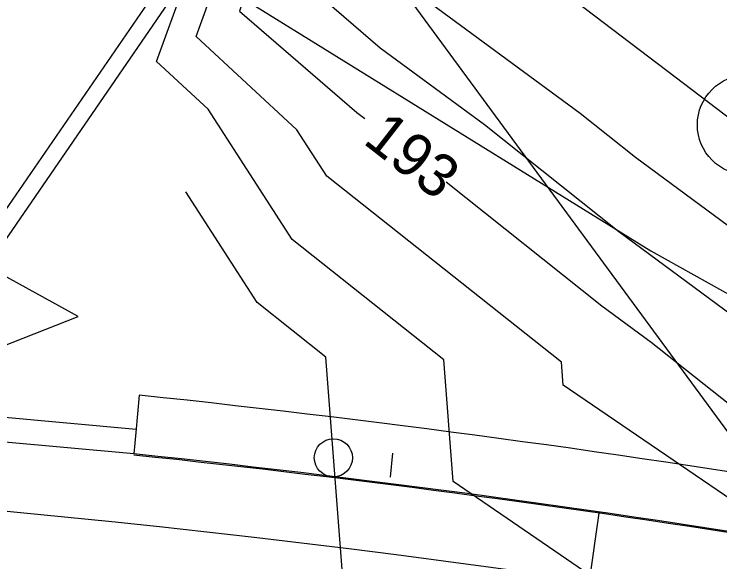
# Model space of a CAD drawing. Extents: x 1385284 to 1385995, y 1975154 to 1975620.
# Drawn here: x 1385581.75 to 1385622.84, y 1975494.43 to 1975526.32 of the extents above; entities that cross this region are included whole.
import ezdxf

# ---------------------------------------------------------------- set-up
doc = ezdxf.new("R2010")
doc.units = 0
for name, color, linetype in [('B-Super-Deck', 7, 'Continuous'), ('Default', 7, 'Continuous'), ('DTM CONTOURS_MAJOR', 7, 'Continuous'), ('DTM_CONTOURS_MINOR', 7, 'Continuous'), ('R_Guardrail', 7, 'Continuous'), ('R_Proposed Road', 7, 'Continuous'), ('R_Shld', 7, 'Continuous'), ('S_IRON_PIN', 7, 'Continuous'), ('S_UNDERGROUND_CABLE', 7, 'Continuous'), ('S_WATER_UTILITIES', 7, 'Continuous')]:
    doc.layers.add(name, color=color, linetype=linetype)

msp = doc.modelspace()

# ---------------------------------------------------------------- linework, layer by layer
at = {"layer": 'B-Super-Deck'}
for p, q in [((1385588.853, 1975502.134), (1385578.894, 1975503.042)), ((1385588.838, 1975501.968), (1385588.724, 1975500.723)), ((1385588.724, 1975500.723), (1385578.766, 1975501.631))]:
    msp.add_line(p, q, dxfattribs=at)
at = {"layer": 'Default'}
for p, q in [((1385601.664, 1975544.642), (1385558.992, 1975482.58)), ((1385559.816, 1975482.013), (1385602.488, 1975544.075)), ((1385603.662, 1975499.361), (1385603.791, 1975500.772))]:
    msp.add_line(p, q, dxfattribs=at)
at = {"layer": 'DTM CONTOURS_MAJOR'}
for points in [[(1385603.84, 1975543.794), (1385602.41, 1975541.146), (1385602.075, 1975540.135), (1385601.205, 1975538.235), (1385601.153, 1975536.854), (1385603.587, 1975531.903), (1385602.776, 1975529.562), (1385604.437, 1975528.129), (1385614.7, 1975520.562), (1385617.932, 1975517.988), (1385628.308, 1975510.325), (1385631.416, 1975507.862), (1385642.381, 1975499.714), (1385644.646, 1975497.454), (1385655.57, 1975489.358), (1385657.86, 1975487.03), (1385667.487, 1975479.873), (1385669.851, 1975478.374)], [(1385567.349, 1975435.532), (1385575.643, 1975444.505), (1385584.2, 1975453.764), (1385584.866, 1975454.455), (1385593.445, 1975463.74), (1385594.049, 1975464.365), (1385602.648, 1975473.677), (1385603.227, 1975473.83), (1385603.894, 1975475.512), (1385603.308, 1975476.333), (1385604.191, 1975491.234), (1385600.884, 1975493.495), (1385599.902, 1975506.35), (1385595.893, 1975509.526), (1385591.739, 1975515.976)]]:
    msp.add_lwpolyline(points, dxfattribs=at)
at = {"layer": 'DTM_CONTOURS_MINOR'}
for points in [[(1385562.866, 1975481.018), (1385563.716, 1975498.339), (1385566.287, 1975500.31), (1385572.546, 1975503.642), (1385585.482, 1975508.711), (1385572.018, 1975516.132), (1385577.884, 1975524.056), (1385581.986, 1975529.59), (1385586.864, 1975537.76), (1385589.378, 1975541.298), (1385592.421, 1975550.843), (1385595.925, 1975556.919), (1385603.651, 1975570.298), (1385603.747, 1975570.566), (1385603.842, 1975570.633), (1385603.931, 1975570.594), (1385610.734, 1975574.084), (1385616.057, 1975580.707), (1385617.625, 1975582.015), (1385623.884, 1975585.062), (1385632.559, 1975588.36), (1385643.399, 1975583.605), (1385645.132, 1975583.412)], [(1385617.369, 1975492.225), (1385607.301, 1975499.112), (1385606.759, 1975506.204), (1385597.926, 1975513.203), (1385593.044, 1975520.782), (1385590.045, 1975523.554), (1385593.409, 1975532.864), (1385594.84, 1975537.505), (1385595.303, 1975538.903), (1385601.683, 1975550.713), (1385601.762, 1975550.79), (1385602.065, 1975551.447), (1385602.382, 1975552.155), (1385602.612, 1975552.619), (1385602.984, 1975553.423), (1385609.856, 1975566.014), (1385610.538, 1975566.429), (1385610.608, 1975566.793), (1385616.058, 1975574.533), (1385619.393, 1975578.242), (1385622.579, 1975579.77), (1385630.039, 1975576.498), (1385630.815, 1975576.153)], [(1385629.951, 1975571.07), (1385621.746, 1975574.571), (1385620.16, 1975573.831), (1385614.59, 1975567.03), (1385614.55, 1975566.928), (1385614.23, 1975565.243), (1385610.958, 1975563.25), (1385606.701, 1975555.45), (1385605.583, 1975553.037), (1385604.893, 1975551.643), (1385603.941, 1975549.518), (1385603.033, 1975547.546), (1385602.794, 1975547.314), (1385598.857, 1975540.024), (1385597.975, 1975537.363), (1385597.843, 1975537.074), (1385597.835, 1975536.864), (1385598.205, 1975536.11), (1385594.871, 1975526.487), (1385601.698, 1975520.596), (1385602.165, 1975520.252)], [(1385625.464, 1975571.006), (1385622.697, 1975572.187), (1385619.09, 1975570.502), (1385617.649, 1975568.743), (1385616.089, 1975564.721), (1385616.076, 1975564.65), (1385611.51, 1975561.868), (1385608.56, 1975556.464), (1385607.069, 1975553.246), (1385606.148, 1975551.388), (1385604.88, 1975548.554), (1385603.668, 1975545.924), (1385603.35, 1975545.614), (1385600.633, 1975540.585), (1385600.025, 1975538.749), (1385599.524, 1975537.654), (1385599.494, 1975536.859), (1385600.896, 1975534.007), (1385598.824, 1975528.024), (1385603.067, 1975524.362), (1385609.13, 1975519.893), (1385616.946, 1975513.668), (1385623.574, 1975508.772)], [(1385629.373, 1975493.57), (1385625.229, 1975496.854), (1385613.718, 1975504.728), (1385613.616, 1975506.059), (1385599.959, 1975516.88), (1385598.212, 1975519.591), (1385592.342, 1975525.015), (1385593.897, 1975529.32), (1385596.302, 1975537.115), (1385597.08, 1975539.464), (1385602.239, 1975549.013), (1385602.397, 1975549.168), (1385603.003, 1975550.482), (1385603.637, 1975551.899), (1385604.098, 1975552.828), (1385604.843, 1975554.436), (1385610.407, 1975564.632), (1385612.384, 1975565.836), (1385612.585, 1975566.89), (1385615.274, 1975570.71), (1385615.989, 1975571.504)], [(1385623.453, 1975555.61), (1385614.29, 1975559.46), (1385613.233, 1975559.187), (1385613.147, 1975559.43), (1385612.612, 1975559.104), (1385612.277, 1975558.491), (1385610.041, 1975553.664), (1385608.659, 1975550.876), (1385606.756, 1975546.625), (1385604.938, 1975542.679), (1385604.462, 1975542.216), (1385604.187, 1975541.707), (1385604.125, 1975541.521), (1385602.886, 1975538.815), (1385602.88, 1975538.66), (1385603.48, 1975537.236), (1385604.253, 1975534.51), (1385611.283, 1975529.471), (1385619.738, 1975523.045), (1385629.376, 1975515.719)], [(1385606.898, 1975516.565), (1385615.959, 1975509.347), (1385618.84, 1975507.219), (1385630.054, 1975498.334), (1385633.931, 1975495.453), (1385642.395, 1975487.011)]]:
    msp.add_lwpolyline(points, dxfattribs=at)
at = {"layer": 'R_Guardrail'}
msp.add_circle((1385600.333, 1975500.493), 1.109, dxfattribs=at)
msp.add_arc((1385514.363, 1974795.136), 709.494, 80.374587, 83.983855, dxfattribs=at)
at = {"layer": 'R_Proposed Road'}
msp.add_line((1385615.796, 1975497.271), (1385615.224, 1975493.312), dxfattribs=at)
msp.add_arc((1385514.357, 1974795.066), 705.494, 77.498258, 106.368381, dxfattribs=at)
at = {"layer": 'R_Shld'}
msp.add_line((1385589.036, 1975504.139), (1385588.838, 1975501.968), dxfattribs=at)
for radius, start, end in [(712.994, 80.375023, 83.98782), (709.494, 77.498258, 83.983855)]:
    msp.add_arc((1385514.357, 1974795.066), radius, start, end, dxfattribs=at)
at = {"layer": 'S_IRON_PIN'}
msp.add_circle((1385624.433, 1975519.877), 2.907, dxfattribs=at)
at = {"layer": 'S_UNDERGROUND_CABLE'}
for p, q in [((1385526.194, 1975569.941), (1385618.813, 1975512.534)), ((1385618.813, 1975512.534), (1385717.289, 1975457.779))]:
    msp.add_line(p, q, dxfattribs=at)
at = {"layer": 'S_WATER_UTILITIES'}
msp.add_line((1385597.304, 1975537.347), (1385661.421, 1975450.098), dxfattribs=at)

# ---------------------------------------------------------------- texts
at = {"layer": 'Default'}
msp.add_text('193', height=2.5, rotation=322.0793, dxfattribs=at).set_placement((1385601.988, 1975518.846))

doc.saveas('drawing.dxf')
